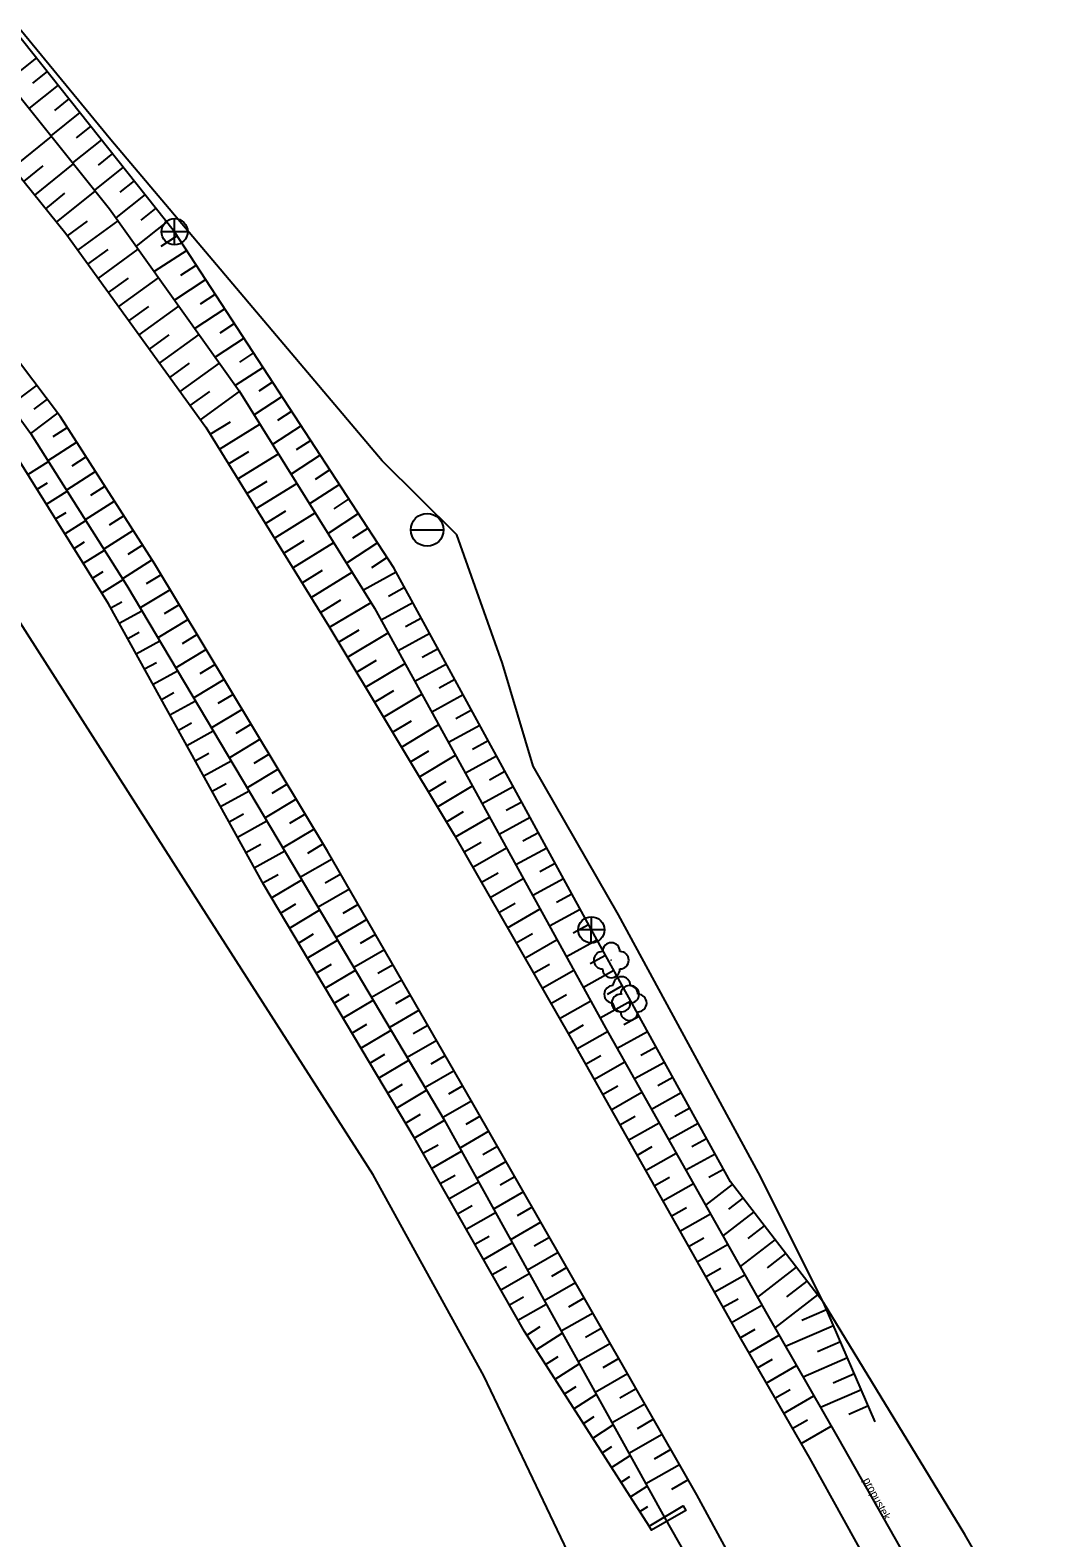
# Model space of a CAD drawing. Extents: x -747135 to -746147, y -1093269 to -1091735.
# Drawn here: x -746724.7 to -746666.5, y -1092501.6 to -1092415.2 of the extents above; entities that cross this region are included whole.
import ezdxf

# ---------------------------------------------------------------- set-up
doc = ezdxf.new("R2010")
doc.units = 0
for name, color, linetype in [('101', 7, 'Continuous'), ('1016', 7, 'Continuous'), ('105', 7, 'Continuous'), ('23700', 7, 'Continuous'), ('306', 7, 'Continuous'), ('316', 7, 'Continuous'), ('424', 7, 'Continuous'), ('803', 7, 'Continuous')]:
    doc.layers.add(name, color=color, linetype=linetype)

msp = doc.modelspace()

# ---------------------------------------------------------------- linework, layer by layer
at = {"layer": '101'}
for points in [[(-746676.31, -1092494.93), (-746679.28, -1092488.1), (-746684.61, -1092481.19), (-746692.58, -1092466.75), (-746703.9, -1092446.01), (-746716.46, -1092426.76), (-746727.325, -1092413.107), (-746739.95, -1092401.9), (-746747.98, -1092394.64), (-746752.03, -1092391.71), (-746753.83, -1092389.76), (-746758.64, -1092386.23), (-746765.82, -1092381.07), (-746787.5, -1092365.52), (-746806.41, -1092354.03)], [(-746807.12, -1092355.24), (-746796.58, -1092362.79), (-746786.63, -1092368.73), (-746775.02, -1092376.93), (-746764.6, -1092384.11), (-746753.89, -1092392.74), (-746744.6, -1092400.27), (-746734.99, -1092408.91), (-746726.93, -1092417.05), (-746720.19, -1092425.45), (-746712.76, -1092435.88), (-746705, -1092448.32), (-746698.55, -1092460.04), (-746691.76, -1092472.37), (-746682.53, -1092488.74), (-746678.42, -1092495.91)], [(-746742.5, -1092417.34), (-746737.93, -1092421.69), (-746731.41, -1092429.1), (-746724.72, -1092438.31), (-746719.2, -1092447.02), (-746709.7, -1092462.98), (-746701.01, -1092477.63), (-746694.64, -1092489.15), (-746688.39, -1092500.4)], [(-746724.38, -1092416.808), (-746726.055, -1092418.141)], [(-746723.134, -1092418.373), (-746724.803, -1092419.701)], [(-746723.757, -1092417.591), (-746724.593, -1092418.256)], [(-746689.26, -1092500.91), (-746696.41, -1092489.76), (-746702.72, -1092478.69), (-746711.35, -1092464.17), (-746720.24, -1092448.07), (-746725.88, -1092439.04), (-746732.66, -1092430.19), (-746738.76, -1092422.69), (-746743.86, -1092418.82)], [(-746722.512, -1092419.155), (-746723.344, -1092419.818)], [(-746721.889, -1092419.938), (-746723.551, -1092421.261)], [(-746721.266, -1092420.72), (-746722.096, -1092421.381)], [(-746725.734, -1092423.111), (-746723.51, -1092421.312)], [(-746720.644, -1092421.503), (-746722.3, -1092422.821)], [(-746720.021, -1092422.285), (-746720.847, -1092422.943)], [(-746725.104, -1092423.889), (-746723.994, -1092422.99)], [(-746724.475, -1092424.666), (-746722.259, -1092422.872)], [(-746719.398, -1092423.068), (-746721.048, -1092424.381)], [(-746723.217, -1092426.221), (-746721.007, -1092424.432)], [(-746718.776, -1092423.85), (-746719.599, -1092424.505)], [(-746723.846, -1092425.443), (-746722.74, -1092424.548)], [(-746718.153, -1092424.633), (-746719.825, -1092425.963)], [(-746722.596, -1092427.004), (-746721.441, -1092426.167)], [(-746722.009, -1092427.814), (-746719.698, -1092426.14)], [(-746716.907, -1092426.198), (-746718.662, -1092427.594)], [(-746717.53, -1092425.415), (-746718.387, -1092426.097)], [(-746716.306, -1092426.996), (-746717.256, -1092427.615)], [(-746721.423, -1092428.624), (-746720.27, -1092427.789)], [(-746720.836, -1092429.434), (-746718.538, -1092427.769)], [(-746715.76, -1092427.833), (-746717.625, -1092429.05)], [(-746715.213, -1092428.671), (-746716.129, -1092429.268)], [(-746720.25, -1092430.244), (-746719.104, -1092429.414)], [(-746719.663, -1092431.054), (-746717.377, -1092429.398)], [(-746714.667, -1092429.508), (-746716.464, -1092430.681)], [(-746714.12, -1092430.346), (-746715.002, -1092430.921)], [(-746719.077, -1092431.864), (-746717.937, -1092431.038)], [(-746718.491, -1092432.674), (-746716.217, -1092431.027)], [(-746713.574, -1092431.183), (-746715.303, -1092432.311)], [(-746713.028, -1092432.021), (-746713.875, -1092432.573)], [(-746717.904, -1092433.484), (-746716.77, -1092432.663)], [(-746717.318, -1092434.294), (-746715.056, -1092432.656)], [(-746712.481, -1092432.858), (-746714.141, -1092433.941)], [(-746711.935, -1092433.696), (-746712.748, -1092434.226)], [(-746716.731, -1092435.103), (-746715.604, -1092434.287)], [(-746716.145, -1092435.913), (-746713.896, -1092434.285)], [(-746711.388, -1092434.533), (-746712.98, -1092435.572)], [(-746724.361, -1092435.55), (-746725.886, -1092436.705)], [(-746710.842, -1092435.371), (-746711.636, -1092435.889)], [(-746723.757, -1092436.347), (-746724.528, -1092436.931)], [(-746715.558, -1092436.723), (-746714.437, -1092435.912)], [(-746714.972, -1092437.533), (-746712.738, -1092435.916)], [(-746710.295, -1092436.208), (-746711.902, -1092437.256)], [(-746723.153, -1092437.144), (-746724.711, -1092438.324)], [(-746709.749, -1092437.046), (-746710.561, -1092437.575)], [(-746722.597, -1092437.975), (-746723.428, -1092438.506)], [(-746714.415, -1092438.363), (-746713.259, -1092437.648)], [(-746713.889, -1092439.214), (-746711.574, -1092437.782)], [(-746709.203, -1092437.883), (-746710.843, -1092438.953)], [(-746722.059, -1092438.817), (-746723.724, -1092439.881)], [(-746708.656, -1092438.721), (-746709.485, -1092439.261)], [(-746724.865, -1092440.666), (-746723.691, -1092439.933)], [(-746721.52, -1092439.66), (-746722.355, -1092440.193)], [(-746713.363, -1092440.064), (-746712.203, -1092439.347)], [(-746712.837, -1092440.915), (-746710.515, -1092439.479)], [(-746708.11, -1092439.558), (-746709.784, -1092440.651)], [(-746720.982, -1092440.502), (-746722.654, -1092441.571)], [(-746707.563, -1092440.396), (-746708.409, -1092440.947)], [(-746724.335, -1092441.514), (-746723.746, -1092441.146)], [(-746723.805, -1092442.362), (-746722.621, -1092441.622)], [(-746720.443, -1092441.345), (-746721.281, -1092441.88)], [(-746712.311, -1092441.765), (-746711.148, -1092441.046)], [(-746711.785, -1092442.616), (-746709.457, -1092441.176)], [(-746707.017, -1092441.233), (-746708.725, -1092442.348)], [(-746719.905, -1092442.188), (-746721.583, -1092443.26)], [(-746706.47, -1092442.071), (-746707.333, -1092442.634)], [(-746723.275, -1092443.21), (-746722.68, -1092442.839)], [(-746722.746, -1092444.058), (-746721.55, -1092443.312)], [(-746719.366, -1092443.03), (-746720.207, -1092443.568)], [(-746711.259, -1092443.466), (-746710.093, -1092442.745)], [(-746710.733, -1092444.317), (-746708.398, -1092442.873)], [(-746705.924, -1092442.908), (-746707.667, -1092444.045)], [(-746718.828, -1092443.873), (-746720.512, -1092444.949)], [(-746705.377, -1092443.746), (-746706.257, -1092444.32)], [(-746722.216, -1092444.906), (-746721.615, -1092444.531)], [(-746721.686, -1092445.755), (-746720.48, -1092445.001)], [(-746718.289, -1092444.716), (-746719.133, -1092445.255)], [(-746710.207, -1092445.167), (-746709.038, -1092444.444)], [(-746709.681, -1092446.018), (-746707.339, -1092444.57)], [(-746704.831, -1092444.583), (-746706.608, -1092445.742)], [(-746717.751, -1092445.558), (-746719.442, -1092446.639)], [(-746704.285, -1092445.421), (-746705.182, -1092446.006)], [(-746721.156, -1092446.603), (-746720.55, -1092446.224)], [(-746720.627, -1092447.451), (-746719.409, -1092446.69)], [(-746717.228, -1092446.411), (-746718.088, -1092446.928)], [(-746709.155, -1092446.868), (-746707.983, -1092446.143)], [(-746708.629, -1092447.719), (-746706.281, -1092446.267)], [(-746703.758, -1092446.27), (-746705.639, -1092447.296)], [(-746716.713, -1092447.268), (-746718.435, -1092448.305)], [(-746703.279, -1092447.148), (-746704.194, -1092447.647)], [(-746720.109, -1092448.306), (-746719.479, -1092447.958)], [(-746719.626, -1092449.182), (-746718.337, -1092448.47)], [(-746716.197, -1092448.124), (-746717.06, -1092448.644)], [(-746708.103, -1092448.569), (-746706.927, -1092447.842)], [(-746707.578, -1092449.42), (-746705.204, -1092447.994)], [(-746702.8, -1092448.026), (-746704.616, -1092449.017)], [(-746715.681, -1092448.981), (-746717.412, -1092450.023)], [(-746702.321, -1092448.903), (-746703.228, -1092449.398)], [(-746719.143, -1092450.057), (-746718.484, -1092449.693)], [(-746718.659, -1092450.933), (-746717.313, -1092450.189)], [(-746715.165, -1092449.838), (-746716.033, -1092450.36)], [(-746707.063, -1092450.277), (-746705.883, -1092449.568)], [(-746706.548, -1092451.134), (-746704.221, -1092449.736)], [(-746701.842, -1092449.781), (-746703.652, -1092450.769)], [(-746714.65, -1092450.695), (-746716.389, -1092451.742)], [(-746701.363, -1092450.659), (-746702.266, -1092451.152)], [(-746718.176, -1092451.808), (-746717.489, -1092451.429)], [(-746717.693, -1092452.683), (-746716.29, -1092451.909)], [(-746714.134, -1092451.551), (-746715.006, -1092452.076)], [(-746706.033, -1092451.992), (-746704.885, -1092451.302)], [(-746705.518, -1092452.849), (-746703.256, -1092451.49)], [(-746700.884, -1092451.537), (-746702.688, -1092452.521)], [(-746713.618, -1092452.408), (-746715.366, -1092453.46)], [(-746700.404, -1092452.414), (-746701.305, -1092452.906)], [(-746717.209, -1092453.559), (-746716.494, -1092453.164)], [(-746716.726, -1092454.434), (-746715.266, -1092453.628)], [(-746713.103, -1092453.265), (-746713.979, -1092453.792)], [(-746705.003, -1092453.706), (-746703.888, -1092453.036)], [(-746704.488, -1092454.563), (-746702.291, -1092453.243)], [(-746699.925, -1092453.292), (-746701.723, -1092454.274)], [(-746712.587, -1092454.122), (-746714.343, -1092455.179)], [(-746699.446, -1092454.17), (-746700.344, -1092454.66)], [(-746716.242, -1092455.31), (-746715.499, -1092454.899)], [(-746715.759, -1092456.185), (-746714.243, -1092455.348)], [(-746712.071, -1092454.978), (-746712.952, -1092455.508)], [(-746703.973, -1092455.42), (-746702.89, -1092454.77)], [(-746703.458, -1092456.278), (-746701.326, -1092454.997)], [(-746698.967, -1092455.048), (-746700.759, -1092456.026)], [(-746711.555, -1092455.835), (-746713.321, -1092456.898)], [(-746698.488, -1092455.925), (-746699.383, -1092456.414)], [(-746715.276, -1092457.061), (-746714.503, -1092456.634)], [(-746714.792, -1092457.936), (-746713.219, -1092457.067)], [(-746711.04, -1092456.692), (-746711.924, -1092457.224)], [(-746702.943, -1092457.135), (-746701.893, -1092456.504)], [(-746702.428, -1092457.992), (-746700.361, -1092456.75)], [(-746698.009, -1092456.803), (-746699.795, -1092457.778)], [(-746710.524, -1092457.549), (-746712.298, -1092458.616)], [(-746697.53, -1092457.681), (-746698.421, -1092458.168)], [(-746714.309, -1092458.811), (-746713.508, -1092458.369)], [(-746713.826, -1092459.687), (-746712.196, -1092458.787)], [(-746710.008, -1092458.405), (-746710.897, -1092458.94)], [(-746701.913, -1092458.849), (-746700.895, -1092458.238)], [(-746701.398, -1092459.706), (-746699.396, -1092458.503)], [(-746697.051, -1092458.559), (-746698.831, -1092459.53)], [(-746709.493, -1092459.262), (-746711.275, -1092460.335)], [(-746696.572, -1092459.437), (-746697.46, -1092459.921)], [(-746713.342, -1092460.562), (-746712.513, -1092460.104)], [(-746712.859, -1092461.438), (-746711.172, -1092460.506)], [(-746708.977, -1092460.119), (-746709.87, -1092460.656)], [(-746700.883, -1092460.563), (-746699.898, -1092459.972)], [(-746700.37, -1092461.422), (-746698.408, -1092460.298)], [(-746696.093, -1092460.314), (-746697.866, -1092461.282)], [(-746708.461, -1092460.976), (-746710.252, -1092462.053)], [(-746695.614, -1092461.192), (-746696.499, -1092461.675)], [(-746712.375, -1092462.313), (-746711.518, -1092461.84)], [(-746711.892, -1092463.188), (-746710.149, -1092462.226)], [(-746707.945, -1092461.832), (-746708.843, -1092462.373)], [(-746699.873, -1092462.29), (-746698.899, -1092461.732)], [(-746699.376, -1092463.157), (-746697.443, -1092462.05)], [(-746695.134, -1092462.07), (-746696.901, -1092463.034)], [(-746707.438, -1092462.694), (-746709.25, -1092463.739)], [(-746694.655, -1092462.948), (-746695.537, -1092463.429)], [(-746711.409, -1092464.064), (-746710.523, -1092463.575)], [(-746710.901, -1092464.925), (-746709.16, -1092463.891)], [(-746706.939, -1092463.56), (-746707.839, -1092464.08)], [(-746698.879, -1092464.025), (-746697.92, -1092463.476)], [(-746698.382, -1092464.893), (-746696.478, -1092463.802)], [(-746694.176, -1092463.825), (-746695.936, -1092464.786)], [(-746706.439, -1092464.427), (-746708.229, -1092465.459)], [(-746693.697, -1092464.703), (-746694.576, -1092465.183)], [(-746710.39, -1092465.785), (-746709.52, -1092465.268)], [(-746709.879, -1092466.645), (-746708.14, -1092465.611)], [(-746705.939, -1092465.293), (-746706.829, -1092465.806)], [(-746697.884, -1092465.761), (-746696.94, -1092465.219)], [(-746697.387, -1092466.628), (-746695.513, -1092465.554)], [(-746693.218, -1092465.581), (-746694.972, -1092466.538)], [(-746705.44, -1092466.159), (-746707.209, -1092467.179)], [(-746692.739, -1092466.459), (-746693.614, -1092466.936)], [(-746709.368, -1092467.504), (-746708.499, -1092466.987)], [(-746708.857, -1092468.364), (-746707.119, -1092467.331)], [(-746704.94, -1092467.025), (-746705.82, -1092467.533)], [(-746696.89, -1092467.496), (-746695.961, -1092466.963)], [(-746696.393, -1092468.364), (-746694.548, -1092467.307)], [(-746692.257, -1092467.335), (-746694.002, -1092468.298)], [(-746704.441, -1092467.892), (-746706.189, -1092468.9)], [(-746691.774, -1092468.21), (-746692.647, -1092468.692)], [(-746708.346, -1092469.223), (-746707.478, -1092468.707)], [(-746707.836, -1092470.083), (-746706.099, -1092469.051)], [(-746703.941, -1092468.758), (-746704.81, -1092469.259)], [(-746695.896, -1092469.231), (-746694.981, -1092468.707)], [(-746695.399, -1092470.099), (-746693.583, -1092469.059)], [(-746691.291, -1092469.086), (-746693.038, -1092470.05)], [(-746703.442, -1092469.624), (-746705.168, -1092470.62)], [(-746690.808, -1092469.961), (-746691.681, -1092470.444)], [(-746707.325, -1092470.943), (-746706.457, -1092470.427)], [(-746706.814, -1092471.802), (-746705.079, -1092470.771)], [(-746702.942, -1092470.491), (-746703.8, -1092470.985)], [(-746694.902, -1092470.967), (-746694.001, -1092470.451)], [(-746694.405, -1092471.834), (-746692.619, -1092470.811)], [(-746690.324, -1092470.837), (-746692.073, -1092471.802)], [(-746702.442, -1092471.357), (-746704.148, -1092472.34)], [(-746689.841, -1092471.712), (-746690.714, -1092472.194)], [(-746706.303, -1092472.662), (-746705.436, -1092472.147)], [(-746705.792, -1092473.522), (-746704.058, -1092472.491)], [(-746701.943, -1092472.223), (-746702.79, -1092472.712)], [(-746693.908, -1092472.702), (-746693.022, -1092472.195)], [(-746693.415, -1092473.572), (-746691.646, -1092472.572)], [(-746689.358, -1092472.588), (-746691.096, -1092473.547)], [(-746701.443, -1092473.089), (-746703.127, -1092474.061)], [(-746688.875, -1092473.463), (-746689.74, -1092473.941)], [(-746705.281, -1092474.381), (-746704.414, -1092473.866)], [(-746704.77, -1092475.241), (-746703.038, -1092474.211)], [(-746700.944, -1092473.956), (-746701.78, -1092474.438)], [(-746692.922, -1092474.442), (-746692.039, -1092473.943)], [(-746692.43, -1092475.313), (-746690.664, -1092474.314)], [(-746688.391, -1092474.339), (-746690.114, -1092475.29)], [(-746700.444, -1092474.822), (-746702.107, -1092475.781)], [(-746687.908, -1092475.214), (-746688.765, -1092475.688)], [(-746704.259, -1092476.101), (-746703.393, -1092475.586)], [(-746703.748, -1092476.96), (-746702.017, -1092475.932)], [(-746699.945, -1092475.688), (-746700.771, -1092476.165)], [(-746691.938, -1092476.183), (-746691.055, -1092475.684)], [(-746691.445, -1092477.054), (-746689.682, -1092476.056)], [(-746687.425, -1092476.09), (-746689.132, -1092477.032)], [(-746699.445, -1092476.555), (-746701.086, -1092477.501)], [(-746686.942, -1092476.965), (-746687.791, -1092477.434)], [(-746703.237, -1092477.82), (-746702.372, -1092477.306)], [(-746702.726, -1092478.679), (-746700.998, -1092477.652)], [(-746698.948, -1092477.422), (-746699.774, -1092477.896)], [(-746690.953, -1092477.924), (-746690.072, -1092477.426)], [(-746690.461, -1092478.795), (-746688.699, -1092477.798)], [(-746686.459, -1092477.841), (-746688.149, -1092478.774)], [(-746698.45, -1092478.29), (-746700.117, -1092479.245)], [(-746685.975, -1092478.716), (-746686.817, -1092479.181)], [(-746702.231, -1092479.548), (-746701.364, -1092479.054)], [(-746701.736, -1092480.417), (-746700.012, -1092479.434)], [(-746697.953, -1092479.157), (-746698.793, -1092479.639)], [(-746689.969, -1092479.665), (-746689.088, -1092479.167)], [(-746689.476, -1092480.535), (-746687.717, -1092479.54)], [(-746685.492, -1092479.592), (-746687.167, -1092480.516)], [(-746697.456, -1092480.025), (-746699.149, -1092480.995)], [(-746685.009, -1092480.467), (-746685.842, -1092480.927)], [(-746701.24, -1092481.286), (-746700.384, -1092480.798)], [(-746700.745, -1092482.154), (-746699.044, -1092481.185)], [(-746696.959, -1092480.893), (-746697.812, -1092481.381)], [(-746688.984, -1092481.406), (-746688.105, -1092480.909)], [(-746688.492, -1092482.276), (-746686.735, -1092481.283)], [(-746684.503, -1092481.328), (-746686.04, -1092482.514)], [(-746696.462, -1092481.76), (-746698.181, -1092482.746)], [(-746683.893, -1092482.12), (-746684.718, -1092482.757)], [(-746700.25, -1092483.023), (-746699.405, -1092482.542)], [(-746699.755, -1092483.892), (-746698.076, -1092482.935)], [(-746695.964, -1092482.628), (-746696.831, -1092483.124)], [(-746687.999, -1092483.147), (-746687.121, -1092482.65)], [(-746687.507, -1092484.017), (-746685.752, -1092483.025)], [(-746683.282, -1092482.912), (-746685.048, -1092484.274)], [(-746695.467, -1092483.496), (-746697.213, -1092484.496)], [(-746682.671, -1092483.704), (-746683.611, -1092484.429)], [(-746699.26, -1092484.761), (-746698.426, -1092484.286)], [(-746698.764, -1092485.629), (-746697.109, -1092484.686)], [(-746694.97, -1092484.363), (-746695.85, -1092484.867)], [(-746687.015, -1092484.888), (-746686.138, -1092484.392)], [(-746686.522, -1092485.758), (-746684.77, -1092484.767)], [(-746682.06, -1092484.496), (-746684.055, -1092486.034)], [(-746694.473, -1092485.231), (-746696.245, -1092486.247)], [(-746681.45, -1092485.287), (-746682.504, -1092486.101)], [(-746698.269, -1092486.498), (-746697.447, -1092486.03)], [(-746697.774, -1092487.367), (-746696.141, -1092486.436)], [(-746693.976, -1092486.098), (-746694.869, -1092486.61)], [(-746686.03, -1092486.628), (-746685.155, -1092486.133)], [(-746685.538, -1092487.499), (-746683.788, -1092486.509)], [(-746680.839, -1092486.079), (-746683.063, -1092487.795)], [(-746693.479, -1092486.966), (-746695.278, -1092487.997)], [(-746680.228, -1092486.871), (-746681.397, -1092487.773)], [(-746697.279, -1092488.236), (-746696.468, -1092487.774)], [(-746696.784, -1092489.105), (-746695.173, -1092488.186)], [(-746692.981, -1092487.834), (-746693.887, -1092488.353)], [(-746685.045, -1092488.369), (-746684.171, -1092487.875)], [(-746684.553, -1092489.24), (-746682.806, -1092488.251)], [(-746679.617, -1092487.663), (-746682.065, -1092489.551)], [(-746692.485, -1092488.702), (-746694.31, -1092489.745)], [(-746679.101, -1092488.511), (-746680.526, -1092489.13)], [(-746696.277, -1092489.967), (-746695.506, -1092489.472)], [(-746695.738, -1092490.809), (-746694.249, -1092489.854)], [(-746691.988, -1092489.57), (-746692.906, -1092490.094)], [(-746684.061, -1092490.11), (-746683.186, -1092489.615)], [(-746683.562, -1092490.977), (-746681.822, -1092489.974)], [(-746678.703, -1092489.428), (-746681.451, -1092490.623)], [(-746691.492, -1092490.438), (-746693.338, -1092491.493)], [(-746678.304, -1092490.345), (-746679.627, -1092490.92)], [(-746695.198, -1092491.65), (-746694.48, -1092491.19)], [(-746694.658, -1092492.492), (-746693.276, -1092491.606)], [(-746690.996, -1092491.306), (-746691.924, -1092491.837)], [(-746683.063, -1092491.843), (-746682.194, -1092491.343)], [(-746682.564, -1092492.71), (-746680.828, -1092491.71)], [(-746677.905, -1092491.262), (-746680.45, -1092492.368)], [(-746690.5, -1092492.174), (-746692.367, -1092493.242)], [(-746677.506, -1092492.179), (-746678.728, -1092492.71)], [(-746694.118, -1092493.334), (-746693.454, -1092492.908)], [(-746693.578, -1092494.176), (-746692.303, -1092493.357)], [(-746690.004, -1092493.043), (-746690.942, -1092493.579)], [(-746682.064, -1092493.576), (-746681.197, -1092493.077)], [(-746681.565, -1092494.443), (-746679.833, -1092493.445)], [(-746677.108, -1092493.096), (-746679.449, -1092494.114)], [(-746689.507, -1092493.911), (-746691.396, -1092494.99)], [(-746676.709, -1092494.013), (-746677.829, -1092494.5)], [(-746693.039, -1092495.017), (-746692.427, -1092494.625)], [(-746692.499, -1092495.859), (-746691.329, -1092495.109)], [(-746689.011, -1092494.779), (-746689.96, -1092495.322)], [(-746681.066, -1092495.309), (-746680.201, -1092494.811)], [(-746680.567, -1092496.176), (-746678.839, -1092495.18)], [(-746688.515, -1092495.647), (-746690.424, -1092496.738)], [(-746691.959, -1092496.701), (-746691.401, -1092496.343)], [(-746691.419, -1092497.543), (-746690.356, -1092496.861)], [(-746688.019, -1092496.515), (-746688.979, -1092497.064)], [(-746687.522, -1092497.384), (-746689.453, -1092498.487)], [(-746690.879, -1092498.385), (-746690.374, -1092498.061)], [(-746690.34, -1092499.226), (-746689.383, -1092498.613)], [(-746687.026, -1092498.252), (-746687.997, -1092498.806)], [(-746689.8, -1092500.068), (-746689.348, -1092499.778)]]:
    msp.add_lwpolyline(points, dxfattribs=at)
at = {"layer": '1016'}
for points in [[(-746808.227, -1092357.17), (-746797.53, -1092364.29), (-746787.69, -1092371.13), (-746776.62, -1092378.78), (-746765.54, -1092386.79), (-746755.3, -1092394.62), (-746745.57, -1092402.66), (-746737.91, -1092409.79), (-746728.85, -1092419.26), (-746722.7, -1092426.86), (-746714.67, -1092437.95), (-746707.62, -1092449.35), (-746700.44, -1092461.3), (-746693.84, -1092472.82), (-746684.01, -1092490.2), (-746680.08, -1092497.02)], [(-746686.53, -1092499.12), (-746692.76, -1092488.22), (-746699.39, -1092476.65), (-746707.7, -1092462.24), (-746717.59, -1092445.81), (-746722.99, -1092437.36), (-746730.18, -1092427.87), (-746736.68, -1092420.23), (-746741.31, -1092415.91)], [(-746680.08, -1092497.02), (-746676.15, -1092504.12)], [(-746677.329, -1092516.059), (-746686.53, -1092499.12)], [(-746689.26, -1092500.91), (-746687.32, -1092499.75), (-746687.17, -1092500.01), (-746689.128, -1092501.139), (-746689.26, -1092500.91)]]:
    msp.add_lwpolyline(points, dxfattribs=at)
at = {"layer": '23700'}
for points in [[(-746678.42, -1092495.91), (-746674.28, -1092503.22)], [(-746688.39, -1092500.4), (-746679.03, -1092516.89)]]:
    msp.add_lwpolyline(points, dxfattribs=at)
at = {"layer": '306'}
msp.add_line((-746702.927, -1092443.84), (-746701.052, -1092443.84), dxfattribs=at)
msp.add_circle((-746701.99, -1092443.84), 0.938, dxfattribs=at)
at = {"layer": '316'}
for p, q in [((-746716.461, -1092427.508), (-746716.46, -1092426.013)), ((-746715.708, -1092426.766), (-746717.208, -1092426.761)), ((-746691.828, -1092466.756), (-746693.328, -1092466.751)), ((-746692.581, -1092467.498), (-746692.58, -1092466.003))]:
    msp.add_line(p, q, dxfattribs=at)
for centre in [(-746716.46, -1092426.76), (-746692.58, -1092466.75)]:
    msp.add_circle(centre, 0.75, dxfattribs=at)
at = {"layer": '424'}
msp.add_lwpolyline([(-746666.48, -1092509.53), (-746671.18, -1092501.38), (-746679.28, -1092488.1), (-746683.01, -1092480.66), (-746691.02, -1092465.89), (-746695.91, -1092457.38), (-746697.67, -1092451.5), (-746700.29, -1092444.13), (-746704.56, -1092439.88), (-746720.11, -1092421.5), (-746727.2, -1092412.89), (-746738.25, -1092401.15), (-746749.37, -1092389.72), (-746764.79, -1092376.86), (-746776.64, -1092368.43), (-746787.43, -1092361.47), (-746799.53, -1092355.13), (-746817.34, -1092343.1), (-746824.75, -1092337.86), (-746838.2, -1092329.38), (-746851.64, -1092319.28), (-746869.05, -1092306.53), (-746874.05, -1092300.95)], dxfattribs=at)
for centre in [(-746691.44, -1092468.49), (-746690.84, -1092470.44), (-746690.41, -1092470.94)]:
    msp.add_circle(centre, 0.0005, dxfattribs=at)
for centre, start, end in [((-746691.44, -1092467.99), 0, 179.99999), ((-746691.94, -1092468.49), 89.99999, 269.99999), ((-746690.94, -1092468.49), 270, 89.99999), ((-746691.44, -1092468.99), 179.99999, 359.99999), ((-746691.34, -1092470.44), 89.99999, 269.99999), ((-746690.84, -1092469.94), 0, 179.99999), ((-746690.41, -1092470.44), 0, 179.99999), ((-746690.34, -1092470.44), 270, 89.99999), ((-746690.91, -1092470.94), 89.99999, 269.99999), ((-746690.84, -1092470.94), 179.99999, 359.99999), ((-746689.91, -1092470.94), 270, 89.99999), ((-746690.41, -1092471.44), 179.99999, 359.99999)]:
    msp.add_arc(centre, 0.5, start, end, dxfattribs=at)
at = {"layer": '803'}
msp.add_lwpolyline([(-746689.71, -1092511.48), (-746691.52, -1092507.42), (-746698.75, -1092492.3), (-746705.08, -1092480.78), (-746714.94, -1092465.39), (-746724.32, -1092450.72), (-746730.02, -1092441.79), (-746735.89, -1092432.77), (-746739.69, -1092426.99), (-746754.65, -1092434.36)], dxfattribs=at)

# ---------------------------------------------------------------- texts
at = {"layer": '105'}
msp.add_text('propustek', height=0.45, rotation=298.09848, dxfattribs=at).set_placement((-746677.025, -1092498.268))

doc.saveas('drawing.dxf')
